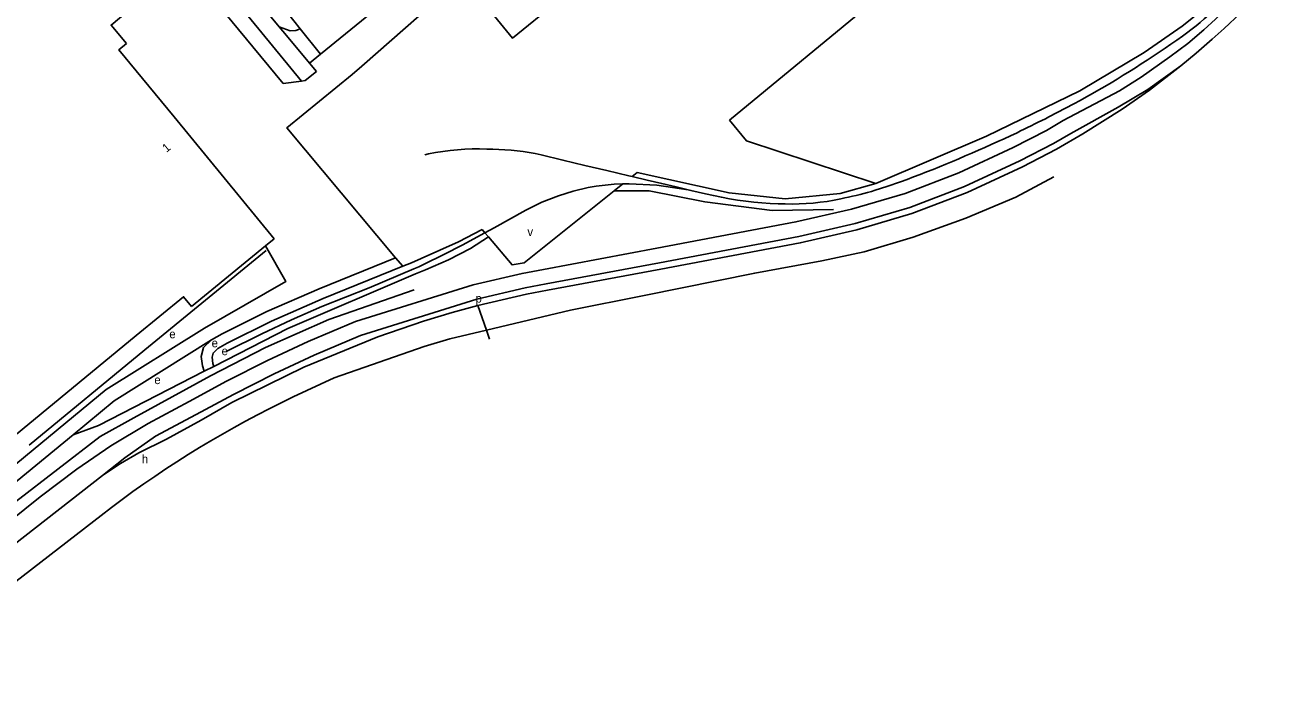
# Model space of a CAD drawing. Extents: x 156097 to 158136, y 385644 to 388348.
# Drawn here: x 157448 to 158044, y 386225 to 386543 of the extents above; entities that cross this region are included whole.
import ezdxf

# ---------------------------------------------------------------- set-up
doc = ezdxf.new("R2010")
doc.units = 0
for name, color, linetype in [('BLT_Basislijn', 7, 'Continuous'), ('BLT_Bebouwing', 7, 'Continuous'), ('BLT_Centroide', 7, 'Continuous'), ('BLT_Huisnummer', 7, 'Continuous'), ('BLT_Spoorlijn', 7, 'Continuous'), ('BLT_Vlakafsluiter', 7, 'Continuous')]:
    doc.layers.add(name, color=color, linetype=linetype)

msp = doc.modelspace()

# ---------------------------------------------------------------- linework, layer by layer
at = {"layer": 'BLT_Basislijn'}
for p, q in [((157516.44, 386618.21), (157577.35, 386541.54)), ((157866.58, 386570.02), (157779.9, 386498.42)), ((157577.35, 386541.54), (157586.84, 386529.59)), ((157581.71, 386525.4), (157584.96, 386521.48)), ((157569.35, 386515.74), (157577.92, 386516.89)), ((157625.73, 386429.61), (157622.23, 386433.59)), ((157625.73, 386429.61), (157629.84, 386431.28)), ((157629.84, 386431.28), (157634.46, 386433.21))]:
    msp.add_line(p, q, dxfattribs=at)
for points in [[(157459.83, 386644.09), (157463.15, 386646.8), (157467.1, 386647.41), (157470.17, 386646.8), (157475.68, 386641.46), (157577.92, 386516.89)], [(157586.84, 386529.59), (157717.36, 386635.88)], [(158044.14, 386617.05), (158035.78, 386592.84), (158020.34, 386567.65), (158009.01, 386555.36), (157993.44, 386542.83), (157975.44, 386530.4), (157945.11, 386512.31), (157901.03, 386491), (157848.87, 386468.63)], [(157509.23, 386612.72), (157518.49, 386601.49), (157567.47, 386542.53)], [(157654.11, 386565.93), (157606.38, 386523.9), (157601.83, 386520.03)], [(157530.96, 386562.26), (157569.35, 386515.74)], [(157937.31, 386498.26), (157963.77, 386512.3), (157974.11, 386518.81), (157987.54, 386528.29), (157996.13, 386534.66), (158003.64, 386541.12), (158009.16, 386546.14), (158016.72, 386553.31)], [(157992.83, 386524.14), (158000, 386530.08), (158007.62, 386536.62), (158013.24, 386541.75), (158020.85, 386548.96)], [(157577.35, 386541.54), (157575.22, 386540.68), (157572.56, 386540.55), (157567.47, 386542.53)], [(157567.47, 386542.53), (157570.93, 386538.37), (157581.71, 386525.4)], [(157484.12, 386331.01), (157494.56, 386339.31), (157509.01, 386349.46), (157528.24, 386359.68), (157545.8, 386369.22), (157564.99, 386378.89), (157583.95, 386387.69), (157605.78, 386396.93), (157660.72, 386414.13), (157683.45, 386419.37), (157693.44, 386421.27), (157746.88, 386431.27), (157812.61, 386443.64), (157839.12, 386449.7), (157864.94, 386457.33), (157890.71, 386467.25), (157916.75, 386479.25), (157932.72, 386487.48), (157940.84, 386492.21), (157963.24, 386504.52), (157977.27, 386512.99), (157992.83, 386524.14)], [(157581.71, 386525.4), (157586.84, 386529.59)], [(157661.14, 386411.09), (157684.08, 386416.37), (157694.01, 386418.27), (157747.45, 386428.26), (157813.23, 386440.64), (157839.89, 386446.74), (157865.93, 386454.43), (157891.9, 386464.42), (157918.1, 386476.5), (157934.19, 386484.8), (157946.59, 386492.03), (157965.09, 386503.68), (157977.99, 386512.69), (157992.83, 386524.14)], [(157622.23, 386433.59), (157571.02, 386494.83), (157601.83, 386520.03)], [(157584.96, 386521.48), (157579.71, 386517.13), (157577.92, 386516.89)], [(157937.31, 386498.26), (157929.35, 386493.62), (157913.68, 386485.54), (157887.98, 386473.7), (157862.69, 386463.97), (157837.34, 386456.48), (157811.18, 386450.49), (157745.59, 386438.15), (157692.14, 386428.15), (157682, 386426.22), (157658.89, 386420.9), (157603.36, 386403.5), (157581.12, 386394.09), (157561.95, 386385.19), (157542.55, 386375.42), (157524.92, 386365.84), (157505.55, 386355.55), (157488.03, 386344.94), (157471.92, 386333.99), (157454.7, 386320.86), (157425.56, 386297.7), (157394.41, 386273.85)], [(157848.87, 386468.63), (157787.81, 386488.77), (157779.9, 386498.42)], [(157665.15, 386399.51), (157704.86, 386408.98), (157739.62, 386415.83), (157791.76, 386426.38), (157823.36, 386432.17), (157843.38, 386436.39), (157866.55, 386443.24), (157891.3, 386452.2), (157915.01, 386462.21), (157932.91, 386471.7)], [(157848.87, 386468.63), (157832.14, 386463.83), (157806.15, 386461.39), (157779.64, 386464.14), (157736.24, 386473.76), (157733.89, 386471.89)], [(157725.38, 386465.1), (157682.91, 386431.22), (157677.28, 386430.2), (157666.17, 386443.43)], [(157729.51, 386468.39), (157725.38, 386465.1)], [(157725.38, 386465.1), (157741.99, 386465.1), (157768.24, 386460.05), (157800, 386455.83), (157828.9, 386456.3)], [(157663.25, 386446.91), (157651.94, 386441.16), (157634.46, 386433.21)], [(157664.5, 386445.42), (157663.25, 386446.91)], [(157666.17, 386443.43), (157657.65, 386438), (157647.23, 386432.58), (157636.38, 386427.95)], [(157666.17, 386443.43), (157664.5, 386445.42)], [(157532.15, 386400.43), (157570.59, 386422.46), (157561.02, 386439.17)], [(157536.56, 386382.38), (157536.06, 386383.76), (157535.73, 386386.69), (157536.24, 386388.64), (157538.51, 386390.82), (157542.84, 386393.3), (157563.76, 386403.67), (157588.23, 386414.42), (157625.73, 386429.61)], [(157540.48, 386397.71), (157561.65, 386408.2), (157586.29, 386419.02), (157622.23, 386433.59)], [(157631.77, 386425.99), (157571.54, 386400.3), (157536.56, 386382.38)], [(157636.38, 386427.95), (157631.77, 386425.99)], [(157247.93, 386417.09), (157369.83, 386268.89), (157380.33, 386276.36), (157470.15, 386350.15)], [(157379.83, 386269.15), (157382.98, 386272.4), (157482.89, 386349.34), (157498.88, 386358.13), (157535.09, 386377.98), (157560.94, 386391.26), (157590.86, 386404.43), (157631.12, 386418.48)], [(157484.12, 386331.01), (157492.51, 386336.65), (157501.28, 386341.67), (157514.25, 386348.06), (157530.6, 386357.12), (157545.13, 386365.38), (157579.02, 386382.1), (157614.03, 386396.26), (157635.5, 386403.68), (157649.01, 386407.77), (157661.14, 386411.09)], [(157405.03, 386312.35), (157408.52, 386307.93), (157485.82, 386371.44), (157532.15, 386400.43)], [(157647.88, 386395.38), (157665.15, 386399.51)], [(157470.15, 386350.15), (157489.62, 386366.15), (157535.49, 386394.85)], [(157532.08, 386380.08), (157531.16, 386382.61), (157530.65, 386387.06), (157531.76, 386391.27), (157535.49, 386394.85)], [(157535.49, 386394.85), (157540.48, 386397.71)], [(157573.98, 386367.99), (157593.41, 386377.01), (157635.87, 386391.84), (157647.88, 386395.38)], [(157536.56, 386382.38), (157532.08, 386380.08)], [(157532.08, 386380.08), (157482.13, 386354.49), (157470.15, 386350.15)], [(157573.98, 386367.99), (157568.33, 386365.25), (157562.72, 386362.45), (157557.14, 386359.57), (157551.6, 386356.62), (157546.1, 386353.6), (157540.64, 386350.51), (157535.22, 386347.35), (157529.84, 386344.13), (157524.5, 386340.83), (157519.2, 386337.47), (157513.95, 386334.04), (157508.74, 386330.54), (157503.57, 386326.98), (157498.45, 386323.35), (157493.38, 386319.65), (157488.36, 386315.89), (157483.38, 386312.07), (157480.02, 386309.43)], [(157413.71, 386275.64), (157442.44, 386298.4), (157484.12, 386331.01)], [(157363.68, 386225.28), (157391.27, 386243.03), (157416.4, 386260.53), (157446.7, 386283.7), (157480.02, 386309.43)]]:
    msp.add_lwpolyline(points, dxfattribs=at)
at = {"layer": 'BLT_Bebouwing'}
for p, q in [((157561.02, 386439.17), (157565.1, 386442.5)), ((157526.01, 386410.62), (157561.02, 386439.17))]:
    msp.add_line(p, q, dxfattribs=at)
for points in [[(157661.82, 386572.48), (157666.65, 386566.62), (157700.29, 386594.32), (157719.28, 386571.29), (157677.5, 386537.1), (157654.11, 386565.93)], [(157500, 386553.13), (157488.12, 386543.29), (157495.32, 386534.56)], [(157495.32, 386534.56), (157491.84, 386531.68), (157500, 386521.68), (157517.83, 386500), (157565.1, 386442.5)], [(157437.19, 386345.33), (157500, 386396.91), (157522.28, 386415.19), (157526.01, 386410.62)]]:
    msp.add_lwpolyline(points, dxfattribs=at)
at = {"layer": 'BLT_Spoorlijn'}
for points in [[(158015.99, 386558.35), (158014.35, 386556.52), (158012.67, 386554.72), (158010.95, 386552.95), (158009.2, 386551.21), (158007.42, 386549.5), (158005.61, 386547.83), (158003.77, 386546.19), (158001.9, 386544.58), (158000, 386543.01)], [(157993.59, 386538.12), (158000, 386543.01)], [(157968.49, 386521.4), (157971.32, 386523.19), (157974.14, 386525.01), (157976.95, 386526.83), (157979.74, 386528.68), (157982.53, 386530.54), (157985.31, 386532.41), (157988.08, 386534.3), (157990.84, 386536.2), (157993.59, 386538.12)], [(157942.31, 386506.2), (157945.27, 386507.8), (157948.22, 386509.41), (157951.16, 386511.05), (157954.08, 386512.72), (157956.99, 386514.41), (157959.89, 386516.12), (157962.77, 386517.86), (157965.64, 386519.61), (157968.49, 386521.4)], [(157930.53, 386500), (157942.31, 386506.2)], [(157915.49, 386492.55), (157917.17, 386493.38), (157918.84, 386494.21), (157920.51, 386495.03), (157922.18, 386495.86), (157923.85, 386496.69), (157925.52, 386497.52), (157927.19, 386498.35), (157928.86, 386499.17), (157930.53, 386500)], [(157888.03, 386480.31), (157891.11, 386481.61), (157894.18, 386482.93), (157897.25, 386484.26), (157900.3, 386485.6), (157903.36, 386486.96), (157906.4, 386488.34), (157909.44, 386489.73), (157912.47, 386491.13), (157915.49, 386492.55)], [(157636.09, 386482.16), (157637.81, 386482.54), (157641.21, 386483.19), (157644.63, 386483.74), (157648.06, 386484.18), (157651.51, 386484.52), (157654.97, 386484.75), (157658.43, 386484.88), (157661.88, 386484.9), (157665.33, 386484.82)], [(157665.33, 386484.82), (157668.2, 386484.79), (157671.06, 386484.7), (157673.93, 386484.54), (157676.79, 386484.3), (157679.64, 386484), (157682.49, 386483.63), (157685.32, 386483.18), (157688.14, 386482.68), (157690.95, 386482.1)], [(157690.95, 386482.1), (157701.3, 386479.64), (157711.66, 386477.17), (157722.02, 386474.71), (157732.37, 386472.25), (157733.89, 386471.89)], [(157860.58, 386469.39), (157863.66, 386470.52), (157866.73, 386471.68), (157869.8, 386472.85), (157872.86, 386474.04), (157875.91, 386475.26), (157878.95, 386476.49), (157881.99, 386477.75), (157885.02, 386479.02), (157888.03, 386480.31)], [(157733.89, 386471.89), (157740.99, 386470.21), (157747.86, 386468.6), (157754.74, 386466.99), (157760.29, 386465.69)], [(157729.51, 386468.39), (157725.51, 386468.26), (157716.97, 386467.37), (157713.14, 386466.7), (157706.09, 386465.04), (157699.19, 386462.86), (157691.35, 386459.75), (157683.81, 386455.99), (157668.8, 386447.78), (157664.5, 386445.42)], [(157760.29, 386465.69), (157745.5, 386467.76), (157732.52, 386468.48), (157729.51, 386468.39)], [(157760.29, 386465.69), (157761.62, 386465.38), (157768.5, 386463.76)], [(157832.45, 386461.4), (157834.26, 386461.78), (157836.05, 386462.18), (157837.85, 386462.59), (157839.65, 386463.02), (157841.43, 386463.47), (157843.22, 386463.93), (157845, 386464.41), (157846.77, 386464.91), (157848.54, 386465.42)], [(157848.54, 386465.42), (157854.14, 386467.16), (157860.58, 386469.39)], [(157768.5, 386463.76), (157772.26, 386462.9), (157776.04, 386462.11), (157779.84, 386461.42), (157783.66, 386460.81), (157787.49, 386460.29), (157791.33, 386459.86), (157795.18, 386459.52), (157799.04, 386459.26), (157802.89, 386459.1)], [(157802.89, 386459.1), (157806.18, 386458.96), (157809.49, 386458.92), (157812.79, 386458.98), (157816.1, 386459.13), (157819.4, 386459.39), (157822.69, 386459.75), (157825.96, 386460.2), (157829.22, 386460.75), (157832.45, 386461.4)], [(157664.5, 386445.42), (157653.78, 386439.56), (157645.46, 386435.23), (157635.47, 386430.43)], [(157449.45, 386345.3), (157504.06, 386390.26), (157561.22, 386436.97)], [(157635.47, 386430.43), (157633.32, 386429.39), (157630.9, 386428.37)], [(157630.9, 386428.37), (157609.91, 386419.46), (157587.55, 386410.58), (157573.24, 386404.3), (157559.3, 386397.68), (157542.39, 386389.38)]]:
    msp.add_lwpolyline(points, dxfattribs=at)
at = {"layer": 'BLT_Vlakafsluiter'}
for p, q in [((157665.15, 386399.51), (157661.14, 386411.09)), ((157666.62, 386395.26), (157665.15, 386399.51))]:
    msp.add_line(p, q, dxfattribs=at)

# ---------------------------------------------------------------- texts
at = {"layer": 'BLT_Centroide'}
for s, p in [('v', (157684.53, 386443.87)), ('p', (157660.02, 386412.47)), ('e', (157515.57, 386395.67)), ('e', (157535.54, 386391.42)), ('e', (157540.23, 386387.67)), ('e', (157508.53, 386374.06)), ('h', (157502.58, 386336.75))]:
    msp.add_text(s, height=4, dxfattribs=at).set_placement(p)
at = {"layer": 'BLT_Huisnummer'}
msp.add_text('1', height=4, rotation=39.42632, dxfattribs=at).set_placement((157514.27, 386483.07))

doc.saveas('drawing.dxf')
